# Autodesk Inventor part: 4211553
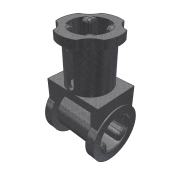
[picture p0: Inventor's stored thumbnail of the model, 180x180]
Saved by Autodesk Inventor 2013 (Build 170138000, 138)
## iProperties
Created: 2013-03
Part Number: 4211553
Material: Generic
Document SubType Name: Modeling
Designer: perblt
Density: 1 g/cm^3
Translation Standard: STEP AP203
FileName: 4211553
PreProcessor: PRO/ENGINEER BY PARAMETRIC TECHNOLOGY CORPORATION, 2010370
PostProcessor: Build: 138, Release: 2013 RTM - Date: Thu 03/01/2012
Sent Units: millimeter
Uncertainty: 0.0019203644892649998
Author: perblt
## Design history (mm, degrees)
node "42115531"
node "4211553"
node "Base1"
